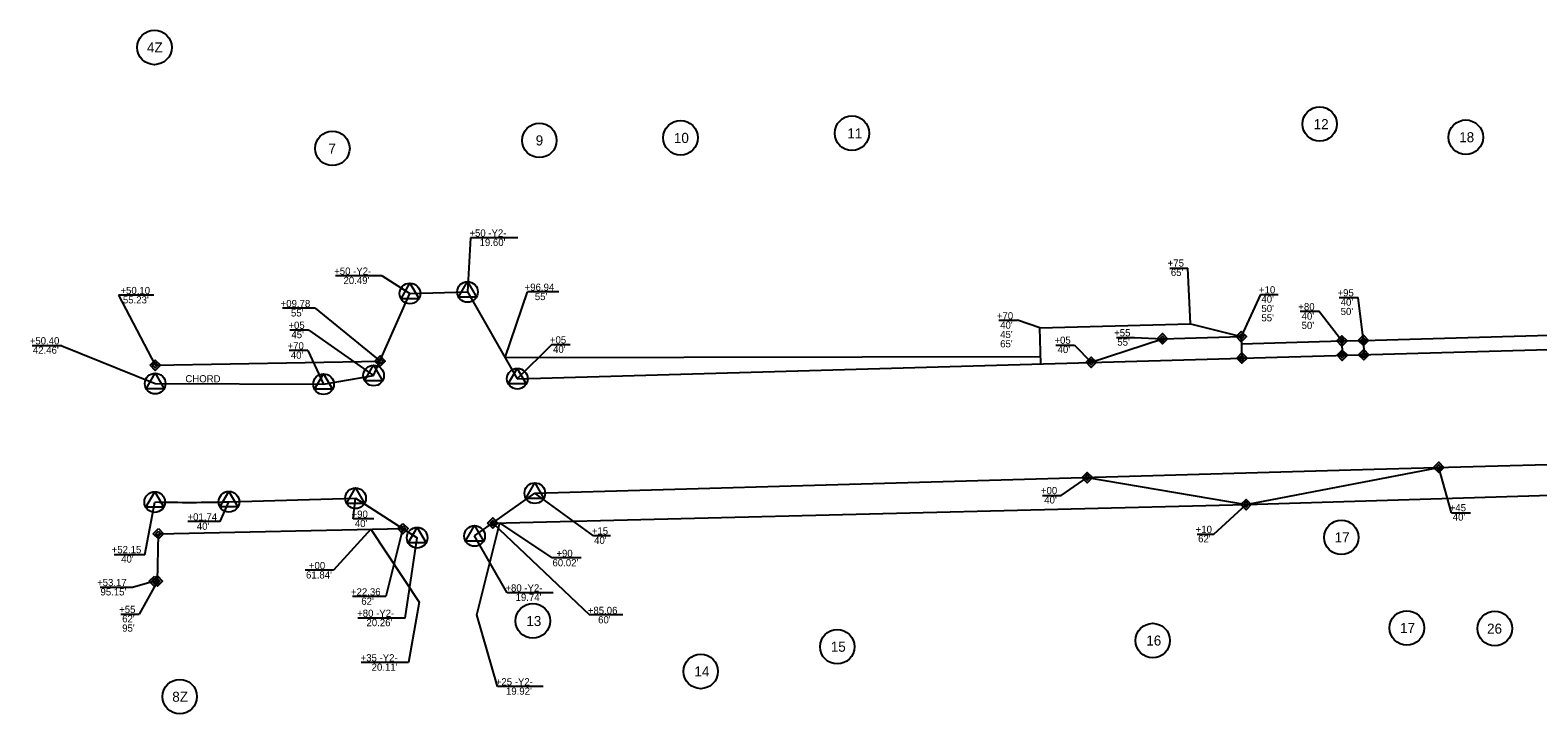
# Model space of a CAD drawing. Extents: x 1756120 to 1760612, y 736784 to 737319.
# Drawn here: x 1757148 to 1758199, y 736784 to 737260 of the extents above; entities that cross this region are included whole.
import ezdxf

# ---------------------------------------------------------------- set-up
doc = ezdxf.new("R2010")
doc.units = 0
for name, color, linetype in [('Prop Easement Construction', 7, 'Continuous'), ('Prop Easement Construction Station Offsets', 7, 'Continuous'), ('Prop Easement Permanent Drainage', 7, 'Continuous'), ('Prop Easement Permanent Drainage Station Offsets', 7, 'Continuous'), ('Prop Easement Permanent Drainage Utility', 7, 'Continuous'), ('Prop Easement Permanent Drainage Utility Station Offsets', 7, 'Continuous'), ('Prop Easement Permanent Utility', 7, 'Continuous'), ('Prop Easement Permanent Utility Station Offsets', 7, 'Continuous'), ('Prop Easement Temporary Drainage', 7, 'Continuous'), ('Prop Easement Temporary Drainage Station Offsets', 7, 'Continuous'), ('Prop Parcel Number CELL', 7, 'Continuous'), ('Prop Parcel Number Text', 7, 'Continuous'), ('Prop ROW Marker CELL', 7, 'Continuous'), ('Prop ROW Permanent Easement CELL', 7, 'Continuous'), ('Prop ROW RW Lines', 7, 'Continuous'), ('Prop ROW Station Offsets', 7, 'Continuous')]:
    doc.layers.add(name, color=color, linetype=linetype)

msp = doc.modelspace()

# ---------------------------------------------------------------- linework, layer by layer
at = {"layer": 'Prop Easement Construction'}
for p, q in [((1758077.2, 737043.7), (1758567, 737057.7)), ((1757992.2, 737041.3), (1758062.2, 737043.3)), ((1758077.2, 737043.7), (1758082.2, 737043.9)), ((1757479.2, 737031.8), (1757852.4, 737032.4)), ((1757459.6, 736852.5), (1757475.5, 736916.6)), ((1757385.6, 736912.2), (1757419.3, 736861.4))]:
    msp.add_line(p, q, dxfattribs=at)
at = {"layer": 'Prop Easement Construction Station Offsets'}
for p, q in [((1757412.9, 737076.3), (1757453, 737077.4)), ((1757479.2, 737031.8), (1757494.8, 737077.4)), ((1757516.5, 737077.4), (1757494.8, 737077.4)), ((1757511.9, 736892.2), (1757475.5, 736916.6)), ((1757385.6, 736912.2), (1757359.6, 736883.7)), ((1757359.6, 736883.7), (1757340, 736883.7)), ((1757532.1, 736892.2), (1757511.9, 736892.2)), ((1757419.3, 736861.4), (1757411.9, 736819.5)), ((1757473.9, 736802.8), (1757459.6, 736852.5)), ((1757411.9, 736819.5), (1757378.9, 736819.5)), ((1757505.8, 736802.8), (1757473.9, 736802.8))]:
    msp.add_line(p, q, dxfattribs=at)
at = {"layer": 'Prop Easement Permanent Drainage'}
for p, q in [((1757887.5, 737028.4), (1757937.1, 737044.8)), ((1757937.1, 737044.8), (1757992.1, 737046.3)), ((1757992.1, 737046.3), (1757992.5, 737031.3)), ((1757235.4, 737026.4), (1757392.1, 737029.3))]:
    msp.add_line(p, q, dxfattribs=at)
at = {"layer": 'Prop Easement Permanent Drainage Station Offsets'}
for p, q in [((1757209.9, 737075.1), (1757235.4, 737026.4)), ((1757234.5, 737075.1), (1757209.9, 737075.1)), ((1758005.4, 737075.7), (1757992.1, 737046.3)), ((1758005.4, 737075.7), (1758017.8, 737075.7)), ((1757346.9, 737066), (1757324.2, 737066)), ((1757346.9, 737066), (1757392.1, 737029.3)), ((1757905.2, 737045.6), (1757917.6, 737045.6)), ((1757917.6, 737045.6), (1757937.1, 737044.8)), ((1757862.9, 737040.3), (1757875.8, 737040.3)), ((1757875.8, 737040.3), (1757887.5, 737028.4))]:
    msp.add_line(p, q, dxfattribs=at)
at = {"layer": 'Prop Easement Permanent Drainage Utility'}
for p, q in [((1757884.8, 736948.2), (1757995.4, 736929.4)), ((1757995.4, 736929.4), (1758129.7, 736955.2)), ((1758138.5, 736923.7), (1758151.7, 736923.7))]:
    msp.add_line(p, q, dxfattribs=at)
at = {"layer": 'Prop Easement Permanent Drainage Utility Station Offsets'}
for p, q in [((1757866.5, 736935.7), (1757884.8, 736948.2)), ((1758138.5, 736923.7), (1758129.7, 736955.2)), ((1757853.5, 736935.7), (1757866.5, 736935.7)), ((1757973, 736908.7), (1757995.4, 736929.4)), ((1757961.3, 736908.7), (1757973, 736908.7))]:
    msp.add_line(p, q, dxfattribs=at)
at = {"layer": 'Prop Easement Permanent Utility'}
for p, q in [((1758062.2, 737043.3), (1758077.2, 737043.7)), ((1758062.2, 737043.3), (1758062.4, 737033.3)), ((1758077.2, 737043.7), (1758077.4, 737033.7)), ((1757995.4, 736929.4), (1758939.9, 736958.2)), ((1757470.6, 736916.5), (1757995.4, 736929.4)), ((1757236.9, 736876.1), (1757237.6, 736909.1)), ((1757237.6, 736909.1), (1757408, 736912.7)), ((1757234.9, 736876), (1757236.9, 736876.1))]:
    msp.add_line(p, q, dxfattribs=at)
at = {"layer": 'Prop Easement Permanent Utility Station Offsets'}
for p, q in [((1758060.3, 737073.6), (1758073.4, 737073.6)), ((1758077.2, 737043.7), (1758073.4, 737073.6)), ((1758033.1, 737063.9), (1758046.1, 737063.9)), ((1758062.2, 737043.3), (1758046.1, 737063.9)), ((1757470.6, 736916.5), (1757538, 736852.5)), ((1757408, 736912.7), (1757396.2, 736865.4)), ((1757234.9, 736876), (1757219.5, 736871.7)), ((1757236.9, 736876.1), (1757224.3, 736853)), ((1757219.5, 736871.7), (1757197, 736871.7)), ((1757396.2, 736865.4), (1757372.9, 736865.4)), ((1757211.4, 736853), (1757224.3, 736853)), ((1757561.2, 736852.5), (1757538, 736852.5))]:
    msp.add_line(p, q, dxfattribs=at)
at = {"layer": 'Prop Easement Temporary Drainage'}
for p, q in [((1757851.8, 737052.4), (1757956.8, 737055.3)), ((1757852.5, 737027.4), (1757851.8, 737052.4)), ((1757956.8, 737055.3), (1757992.1, 737046.3))]:
    msp.add_line(p, q, dxfattribs=at)
at = {"layer": 'Prop Easement Temporary Drainage Station Offsets'}
for p, q in [((1757942.3, 737094), (1757954.8, 737094)), ((1757956.8, 737055.3), (1757954.8, 737094)), ((1757823.2, 737057.7), (1757836.2, 737057.7)), ((1757851.8, 737052.4), (1757836.2, 737057.7))]:
    msp.add_line(p, q, dxfattribs=at)
at = {"layer": 'Prop Parcel Number CELL'}
for centre in [(1757234.9, 737247.6), (1757720.8, 737187.9), (1758046.7, 737194.3), (1757358.9, 737177.3), (1757503.1, 737182.9), (1757601.4, 737184.7), (1758148.5, 737185.1), (1758061.8, 736906.5), (1757498.5, 736848.4), (1758107.4, 736843.5), (1758168.7, 736843.1), (1757710.6, 736830.4), (1757930.4, 736834.7), (1757615.5, 736813.2), (1757252.5, 736795.7)]:
    msp.add_circle(centre, 12, dxfattribs=at)
at = {"layer": 'Prop ROW Marker CELL'}
for p, q in [((1757412.9, 737076.3), (1757412.9, 737076.3)), ((1757453, 737077.4), (1757453, 737077.4)), ((1757937.1, 737044.8), (1757937.1, 737044.8)), ((1757992.1, 737046.3), (1757992.1, 737046.3)), ((1758062.2, 737043.3), (1758062.2, 737043.3)), ((1758077.2, 737043.7), (1758077.2, 737043.7)), ((1757992.5, 737031.3), (1757992.5, 737031.3)), ((1758062.4, 737033.3), (1758062.4, 737033.3)), ((1758077.4, 737033.7), (1758077.4, 737033.7)), ((1757235.4, 737026.4), (1757235.4, 737026.4)), ((1757392.1, 737029.3), (1757392.1, 737029.3)), ((1757887.5, 737028.4), (1757887.5, 737028.4)), ((1757235.4, 737013.6), (1757235.4, 737013.6)), ((1757352.7, 737013.2), (1757352.7, 737013.2)), ((1757387.6, 737019.2), (1757387.6, 737019.2)), ((1757487.7, 737017), (1757487.7, 737017)), ((1757884.8, 736948.2), (1757884.8, 736948.2)), ((1758129.7, 736955.2), (1758129.7, 736955.2)), ((1757499.9, 736937.3), (1757499.9, 736937.3)), ((1757235.1, 736931.1), (1757235.1, 736931.1)), ((1757286.8, 736931.3), (1757286.8, 736931.3)), ((1757375, 736933.8), (1757375, 736933.8)), ((1757995.4, 736929.4), (1757995.4, 736929.4)), ((1757470.6, 736916.5), (1757470.6, 736916.5)), ((1757237.6, 736909.1), (1757237.6, 736909.1)), ((1757408, 736912.7), (1757408, 736912.7)), ((1757417.9, 736906.3), (1757417.9, 736906.3)), ((1757457.9, 736907.5), (1757457.9, 736907.5)), ((1757234.9, 736876), (1757234.9, 736876)), ((1757236.9, 736876.1), (1757236.9, 736876.1))]:
    msp.add_line(p, q, dxfattribs=at)
for points in [[(1757406.7, 737072.7), (1757412.9, 737083.5), (1757419.2, 737072.7)], [(1757446.8, 737073.8), (1757453, 737084.6), (1757459.3, 737073.8)], [(1757229.1, 737010), (1757235.4, 737020.8), (1757241.6, 737010)], [(1757346.5, 737009.6), (1757352.7, 737020.4), (1757359, 737009.6)], [(1757381.3, 737015.6), (1757387.6, 737026.4), (1757393.8, 737015.6)], [(1757481.4, 737013.4), (1757487.7, 737024.2), (1757493.9, 737013.4)], [(1757228.9, 736927.5), (1757235.1, 736938.3), (1757241.4, 736927.5)], [(1757280.5, 736927.7), (1757286.8, 736938.5), (1757293, 736927.7)], [(1757368.7, 736930.2), (1757375, 736941), (1757381.2, 736930.2)], [(1757493.7, 736933.7), (1757499.9, 736944.5), (1757506.2, 736933.7)], [(1757451.6, 736903.9), (1757457.9, 736914.7), (1757464.1, 736903.9)], [(1757411.7, 736902.7), (1757417.9, 736913.5), (1757424.2, 736902.7)]]:
    msp.add_lwpolyline(points, close=True, dxfattribs=at)
for centre in [(1757412.9, 737076.3), (1757453, 737077.4), (1757235.4, 737013.6), (1757352.7, 737013.2), (1757387.6, 737019.2), (1757487.7, 737017), (1757235.1, 736931.1), (1757286.8, 736931.3), (1757375, 736933.8), (1757499.9, 736937.3), (1757457.9, 736907.5), (1757417.9, 736906.3)]:
    msp.add_circle(centre, 7.2, dxfattribs=at)
at = {"layer": 'Prop ROW Permanent Easement CELL'}
for points in [[(1757933.5, 737044.8), (1757937.1, 737048.4), (1757940.7, 737044.8), (1757937.1, 737041.2)], [(1757935.3, 737044.8), (1757937.1, 737046.6), (1757938.9, 737044.8), (1757937.1, 737043)], [(1757988.5, 737046.3), (1757992.1, 737049.9), (1757995.7, 737046.3), (1757992.1, 737042.7)], [(1757990.3, 737046.3), (1757992.1, 737048.1), (1757993.9, 737046.3), (1757992.1, 737044.5)], [(1758058.6, 737043.3), (1758062.2, 737046.9), (1758065.8, 737043.3), (1758062.2, 737039.7)], [(1758060.4, 737043.3), (1758062.2, 737045.1), (1758064, 737043.3), (1758062.2, 737041.5)], [(1758073.6, 737043.7), (1758077.2, 737047.3), (1758080.8, 737043.7), (1758077.2, 737040.1)], [(1758075.4, 737043.7), (1758077.2, 737045.5), (1758079, 737043.7), (1758077.2, 737041.9)], [(1757388.5, 737029.3), (1757392.1, 737032.9), (1757395.7, 737029.3), (1757392.1, 737025.7)], [(1757390.3, 737029.3), (1757392.1, 737031.1), (1757393.9, 737029.3), (1757392.1, 737027.5)], [(1757883.9, 737028.4), (1757887.5, 737032), (1757891.1, 737028.4), (1757887.5, 737024.8)], [(1757885.7, 737028.4), (1757887.5, 737030.2), (1757889.3, 737028.4), (1757887.5, 737026.6)], [(1757988.9, 737031.3), (1757992.5, 737034.9), (1757996.1, 737031.3), (1757992.5, 737027.7)], [(1757990.7, 737031.3), (1757992.5, 737033.1), (1757994.3, 737031.3), (1757992.5, 737029.5)], [(1758058.8, 737033.3), (1758062.4, 737036.9), (1758066, 737033.3), (1758062.4, 737029.7)], [(1758060.6, 737033.3), (1758062.4, 737035.1), (1758064.2, 737033.3), (1758062.4, 737031.5)], [(1758073.8, 737033.7), (1758077.4, 737037.3), (1758081, 737033.7), (1758077.4, 737030.1)], [(1758075.6, 737033.7), (1758077.4, 737035.5), (1758079.2, 737033.7), (1758077.4, 737031.9)], [(1757231.8, 737026.4), (1757235.4, 737030), (1757239, 737026.4), (1757235.4, 737022.8)], [(1757233.6, 737026.4), (1757235.4, 737028.2), (1757237.2, 737026.4), (1757235.4, 737024.6)], [(1758126.1, 736955.2), (1758129.7, 736958.8), (1758133.3, 736955.2), (1758129.7, 736951.6)], [(1758127.9, 736955.2), (1758129.7, 736957), (1758131.5, 736955.2), (1758129.7, 736953.4)], [(1757881.2, 736948.2), (1757884.8, 736951.8), (1757888.4, 736948.2), (1757884.8, 736944.6)], [(1757883, 736948.2), (1757884.8, 736950), (1757886.6, 736948.2), (1757884.8, 736946.4)], [(1757991.8, 736929.4), (1757995.4, 736933), (1757999, 736929.4), (1757995.4, 736925.8)], [(1757993.6, 736929.4), (1757995.4, 736931.2), (1757997.2, 736929.4), (1757995.4, 736927.6)], [(1757408, 736916.3), (1757411.6, 736912.7), (1757408, 736909.1), (1757404.4, 736912.7)], [(1757408, 736914.5), (1757409.8, 736912.7), (1757408, 736910.9), (1757406.2, 736912.7)], [(1757467, 736916.5), (1757470.6, 736920.1), (1757474.2, 736916.5), (1757470.6, 736912.9)], [(1757468.8, 736916.5), (1757470.6, 736918.3), (1757472.4, 736916.5), (1757470.6, 736914.7)], [(1757237.6, 736912.7), (1757241.2, 736909.1), (1757237.6, 736905.5), (1757234, 736909.1)], [(1757237.6, 736910.9), (1757239.4, 736909.1), (1757237.6, 736907.3), (1757235.8, 736909.1)], [(1757234.9, 736879.6), (1757238.5, 736876), (1757234.9, 736872.4), (1757231.3, 736876)], [(1757234.9, 736877.8), (1757236.7, 736876), (1757234.9, 736874.2), (1757233.1, 736876)], [(1757236.9, 736879.7), (1757240.5, 736876.1), (1757236.9, 736872.5), (1757233.3, 736876.1)], [(1757236.9, 736877.9), (1757238.7, 736876.1), (1757236.9, 736874.3), (1757235.1, 736876.1)]]:
    msp.add_lwpolyline(points, close=True, dxfattribs=at)
at = {"layer": 'Prop ROW RW Lines'}
for p, q in [((1757387.6, 737019.2), (1757412.9, 737076.3)), ((1757453, 737077.4), (1757487.7, 737017)), ((1758082.4, 737033.9), (1758847.1, 737055.6)), ((1757487.7, 737017), (1758082.4, 737033.9)), ((1757235.4, 737013.6), (1757352.7, 737013.2)), ((1757352.7, 737013.2), (1757387.6, 737019.2)), ((1758084.7, 736953.9), (1759384.2, 736990.8)), ((1757499.9, 736937.3), (1758084.7, 736953.9)), ((1757457.9, 736907.5), (1757499.9, 736937.3)), ((1757286.8, 736931.3), (1757375, 736933.8)), ((1757375, 736933.8), (1757417.9, 736906.3))]:
    msp.add_line(p, q, dxfattribs=at)
msp.add_arc((1757258.7, 737920.9), 990, 268.6359, 271.6265, dxfattribs=at)
at = {"layer": 'Prop ROW Station Offsets'}
for p, q in [((1757488, 737115.1), (1757455.1, 737115.1)), ((1757393.6, 737088.7), (1757361.1, 737088.7)), ((1757342.5, 737050.8), (1757329.2, 737050.8)), ((1757170.4, 737039.9), (1757149.6, 737039.9)), ((1757170.4, 737039.9), (1757235.4, 737013.6)), ((1757341.7, 737036.6), (1757328.7, 737036.6)), ((1757524.4, 737040.5), (1757511.4, 737040.5)), ((1757228.3, 736894.4), (1757235.1, 736931.1)), ((1757280.6, 736917.5), (1757258.1, 736917.5)), ((1757387.8, 736919.4), (1757373.3, 736919.4)), ((1757552.7, 736907.7), (1757540.8, 736907.7)), ((1757228.3, 736894.4), (1757206.8, 736894.4)), ((1757512.7, 736868), (1757480.6, 736868)), ((1757409.5, 736850.4), (1757376.6, 736850.4))]:
    msp.add_line(p, q, dxfattribs=at)
for points in [[(1757455.1, 737115.1), (1757453, 737077.4)], [(1757393.6, 737088.7), (1757412.9, 737076.3)], [(1757342.5, 737050.8), (1757387.6, 737019.2)], [(1757341.7, 737036.6), (1757352.7, 737013.2)], [(1757511.4, 737040.5), (1757487.7, 737017)], [(1757540.8, 736907.7), (1757499.9, 736937.3)], [(1757280.6, 736917.5), (1757286.8, 736931.3)], [(1757373.3, 736919.4), (1757375, 736933.8)], [(1757409.5, 736850.4), (1757417.9, 736906.3)], [(1757480.6, 736868), (1757457.9, 736907.5)]]:
    msp.add_lwpolyline(points, dxfattribs=at)

# ---------------------------------------------------------------- texts
at = {"layer": 'Prop Easement Construction Station Offsets'}
for s, p in [('+96.94', (1757492.8, 737078.2)), ("55'", (1757499.9, 737071.7)), ('+90', (1757514.9, 736892.9)), ("61.84'", (1757340.5, 736877.9)), ('+00', (1757342.5, 736884.4)), ("60.02'", (1757512.2, 736886.4)), ('+35 -Y2-', (1757378.5, 736820.2)), ("20.11'", (1757386.2, 736813.7)), ('+25 -Y2-', (1757472.7, 736803.5)), ("19.92'", (1757479.8, 736797))]:
    msp.add_text(s, height=5, dxfattribs=at).set_placement(p)
at = {"layer": 'Prop Easement Permanent Drainage Station Offsets'}
for s, p in [('+50.10', (1757211.2, 737075.9)), ("55.23'", (1757212.9, 737069.4)), ('+09.78', (1757322.8, 737066.8)), ("55'", (1757330, 737060.3))]:
    msp.add_text(s, height=5, dxfattribs=at).set_placement(p)
for s, p in [('+10', (1758004.4, 737076.4)), ("40'", (1758006.1, 737069.9)), ("50'", (1758006.1, 737063.4)), ("55'", (1758006.1, 737056.9)), ('+55', (1757903.5, 737046.5)), ('+05', (1757861.9, 737041.3)), ("55'", (1757905.7, 737040)), ("40'", (1757864.1, 737034.8))]:
    msp.add_text(s, height=5, rotation=0, dxfattribs=at).set_placement(p)
at = {"layer": 'Prop Easement Permanent Drainage Utility'}
for s, p in [('+45', (1758137.3, 736924.7)), ("40'", (1758139.4, 736918.2))]:
    msp.add_text(s, height=5, rotation=0, dxfattribs=at).set_placement(p)
at = {"layer": 'Prop Easement Permanent Drainage Utility Station Offsets'}
for s, p in [('+00', (1757852.5, 736936.6)), ("40'", (1757854.8, 736930.1)), ('+10', (1757960.3, 736909.6)), ("62'", (1757962, 736903.1))]:
    msp.add_text(s, height=5, rotation=0, dxfattribs=at).set_placement(p)
at = {"layer": 'Prop Easement Permanent Utility Station Offsets'}
for s, p in [('+95', (1758059.1, 737074.3)), ("40'", (1758061.3, 737067.8)), ('+80', (1758031.8, 737064.6)), ("40'", (1758034.1, 737058.1)), ("50'", (1758061.3, 737061.3)), ("50'", (1758034.1, 737051.6)), ('+55', (1757210.3, 736853.9)), ("62'", (1757212.4, 736847.4)), ("95'", (1757212.4, 736840.9))]:
    msp.add_text(s, height=5, rotation=0, dxfattribs=at).set_placement(p)
for s, p in [('+53.17', (1757194.9, 736872.6)), ("95.15'", (1757197.3, 736866.1)), ('+22.36', (1757371.8, 736866.1)), ("62'", (1757379, 736859.6)), ('+85.06', (1757536.8, 736853.2)), ("60'", (1757544, 736846.7))]:
    msp.add_text(s, height=5, dxfattribs=at).set_placement(p)
at = {"layer": 'Prop Easement Temporary Drainage Station Offsets'}
for s, p in [('+75', (1757940.8, 737095)), ("65'", (1757943, 737088.5)), ('+70', (1757821.8, 737058.3)), ("40'", (1757824.1, 737051.8)), ("45'", (1757824.1, 737045.3)), ("65'", (1757824.1, 737038.8))]:
    msp.add_text(s, height=5, rotation=0, dxfattribs=at).set_placement(p)
at = {"layer": 'Prop Parcel Number Text'}
for s, p in [('4Z', (1757229.7, 737244.1)), ('10', (1757596.8, 737181.1)), ('11', (1757717.6, 737184.3)), ('12', (1758042.5, 737190.7)), ('18', (1758143.9, 737181.6)), ('7', (1757356.1, 737173.7)), ('9', (1757500.5, 737179.4)), ('17', (1758057.1, 736903)), ('13', (1757494, 736844.8)), ('17', (1758102.7, 736840)), ('26', (1758163.3, 736839.5)), ('15', (1757706.1, 736826.9)), ('16', (1757925.9, 736831.2)), ('14', (1757611.1, 736809.7)), ('8Z', (1757247.3, 736792.1))]:
    msp.add_text(s, height=7, rotation=0, dxfattribs=at).set_placement(p)
at = {"layer": 'Prop ROW Station Offsets'}
for s, p in [('+50 -Y2-', (1757454.3, 737115.9)), ("19.60'", (1757461.4, 737109.4)), ('+50 -Y2-', (1757360.1, 737089.4)), ("20.49'", (1757366.6, 737082.9)), ('+05', (1757328.2, 737051.7)), ('+50.40', (1757148, 737040.9)), ('+70', (1757327.6, 737037.4)), ("45'", (1757330.3, 737045.2)), ('+05', (1757510.4, 737041.5)), ("42.46'", (1757150.2, 737034.4)), ("40'", (1757329.9, 737030.9)), ("40'", (1757512.6, 737035)), ('+90', (1757372.2, 736920.2)), ('+01.74', (1757257.9, 736918.3)), ("40'", (1757264.4, 736911.8)), ("40'", (1757374.5, 736913.7)), ('+15', (1757539.6, 736908.5)), ("40'", (1757541.2, 736902)), ('+52.15', (1757205.1, 736895.5)), ("40'", (1757211.7, 736889)), ('+80 -Y2-', (1757479.4, 736868.8)), ("19.74'", (1757486.5, 736862.3)), ('+80 -Y2-', (1757376.1, 736851.2)), ("20.26'", (1757382.6, 736844.7))]:
    msp.add_text(s, height=5, dxfattribs=at).set_placement(p)
msp.add_text('CHORD', height=5, rotation=359.7771, dxfattribs=at).set_placement((1757256.4, 737014.5))

doc.saveas('drawing.dxf')
